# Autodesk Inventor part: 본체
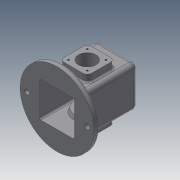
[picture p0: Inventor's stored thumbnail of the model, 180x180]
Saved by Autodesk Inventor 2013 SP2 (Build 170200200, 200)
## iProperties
Created: 2021-08
Part Number: 본체
Material: Generic
Document SubType Name: Modeling
Designer: kumcom8
Density: 1 g/cm^3
Author: kumcom8
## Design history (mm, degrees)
sketch "스케치1"
  geometry: C1 r 67 at (0, 0); 1 further point
  constraints: 1 centre point, 1 coincident
  dimensions: "d0" = 134 diameter of C1
extrude "돌출1" new body sketch "스케치1" distance "d1" = 10; taper "d2" = 0 deg
sketch "스케치2"
  geometry: L1 (-37, -37)-(37, -37); L2 (37, -37)-(37, 37); L3 (37, 37)-(-37, 37); L4 (-37, 37)-(-37, -37); L5 (-37, -37)-(37, 37); L6 (37, -37)-(-37, 37); C1 r 67 at (0, 0) reference
  constraints: 12 end point, 2 midpoint, 2 parallel, 1 horizontal, 1 perpendicular
  dimensions: "d3" = 74 distance of L2.end L3.end; "d5" = 74 distance of L1.end L2.end
extrude "돌출2" join sketch "스케치2" distance "d6" = 100; taper "d7" = 0 deg
sketch "스케치3"
  geometry: L1 (-25, 30)-(25, 30); L2 (25, 30)-(25, 80); L3 (25, 80)-(-25, 80); L4 (-25, 80)-(-25, 30); L5 (-25, 30)-(25, 80); L6 (25, 30)-(-25, 80); L7 (-67, 0)-(67, 0) reference; 3 further points
  constraints: 12 end point, 3 midpoint, 2 parallel, 1 horizontal, 1 perpendicular, 1 vertical alignment
  dimensions: "d8" = 50 distance of L3.end L2.end; "d9" = 50 distance of L2.end L1.end; "d10" = 55 distance from line of L7 point (0, 55)
extrude "돌출3" join sketch "스케치3" stored distance "d11" = 100; taper "d12" = 0 deg
sketch "스케치4"
  geometry: L1 (25, 80)-(-25, 80) reference; L2 (-67, 0)-(67, 0) reference; C1 r 16 at (0, 55); 2 further points
  constraints: 1 centre point, 1 midpoint, 1 vertical alignment
  dimensions: "d13" = 32 diameter of C1; "d14" = 55 distance from line of L2 C1.centre
extrude "돌출4" cut sketch "스케치4" distance "d15" = 110.75; taper "d16" = 0 deg
sketch "스케치5"
  geometry: C1 r 20 at (0, 0); 1 further point
  constraints: 1 centre point, 1 coincident
  dimensions: "d17" = 40 diameter of C1
extrude "돌출5" join sketch "스케치5" distance "d18" = 10; taper "d19" = 0 deg
sketch "스케치6"
  geometry: C1 r 20 at (0, 0) reference; C2 r 10.5 at (0, 0)
  constraints: 1 centre point, 1 coincident
  dimensions: "d20" = 21 diameter of C2
extrude "돌출6" cut sketch "스케치6" distance "d21" = 43.25; taper "d22" = 0 deg
sketch "스케치7"
  geometry: C1 r 10.5 at (0, 0) reference; C2 r 20 at (0, 0) reference; C3 r 14 at (0, 0)
  constraints: 1 centre point, 1 coincident
  dimensions: "d23" = 28 diameter of C3
extrude "돌출7" cut sketch "스케치7" distance "d24" = 4; taper "d25" = 0 deg
feature "면 기울기1" dims angle "d26" = 6 deg
sketch "스케치8"
  geometry: L1 (32, 32)-(-32, 32); L2 (-32, 32)-(-32, -32); L3 (-32, -32)-(32, -32); L4 (32, -32)-(32, 32); L5 (32, 32)-(-32, -32); L6 (-32, 32)-(32, -32); C1 r 67 at (0, 0) reference
  constraints: 12 end point, 2 midpoint, 2 parallel, 1 horizontal, 1 perpendicular
  dimensions: "d27" = 64 distance of L3.end L2.end; "d28" = 64 distance of L2.end L1.end
extrude "돌출8" cut sketch "스케치8" distance "d29" = 105; taper "d30" = 0 deg
sketch "스케치9"
  geometry: C1 r 16 at (32, 55) reference; C2 r 25 at (32, 55); 1 further point
  constraints: 1 centre point, 1 coincident
  dimensions: "d31" = 50 diameter of C2
extrude "돌출9" join sketch "스케치9" distance "d32" = 7; taper "d33" = 0 deg
feature "면 기울기2" dims angle "d34" = 20 deg
feature "면 기울기3" dims angle "d35" = 20 deg
sketch "스케치10"
  geometry: L1 (-17, 38)-(17, 38); L2 (17, 38)-(17, 72); L3 (17, 72)-(-17, 72); L4 (-17, 72)-(-17, 38); L5 (-17, 38)-(17, 72); L6 (17, 38)-(-17, 72); C1 r 16 at (0, 55) reference; 5 further points
  constraints: 12 end point, 4 coincident, 2 midpoint, 2 parallel, 1 horizontal, 1 perpendicular
  dimensions: "d36" = 34 distance of L3.end L2.end; "d37" = 34 distance of L2.end L1.end
hole "구멍1" sketch "스케치10" at (-17, 72), (-17, 38), (17, 38), (17, 72) diameter "d38" = 3.242; stored, may be unused: countersink angle "d42" = 90 deg, drill point angle "d44" = 118 deg; dims "d39" = 8, "d40" = 4, "d41" = 2, "d43" = 10
fillet "모깎기1" dims "d45" = 8
fillet "모깎기2" dims "d46" = 3
sketch "스케치11"
  geometry: C1 r 64 at (0, 0) reference; C2 r 4.5 at (-55, 0); C3 r 4.5 at (55, 0); A1 r 55 centre (0, 0) between (-55, 0) and (55, 0)
  constraints: 3 centre point, 2 point on circle, 1 coincident
  dimensions: "d47" = 110 diameter of A1; "d48" = 9 diameter of C2; "d49" = 9 diameter of C3
extrude "돌출10" cut sketch "스케치11" stored distance "d50" = 7; taper "d51" = 0 deg
node "작업 평면1"
sketch "스케치12"
  geometry: L1 (-37, 102)-(-37, 13) reference; L2 (29, 110)-(-29, 110) reference; L3 (18.949, 120)-(-18.949, 120) reference; 2 further points
  constraints: 1 other
  dimensions: "d53" = 37 distance from line of L1 point (0, 92); "d55" = 28 distance from line of point (0, 92) L3
feature "엠보싱1" sketch "스케치12" dims "d56" = 0.5, "d57" = 0
node "솔리드1"
mirror "대칭1"
mirror "대칭2"
other parameters: "d52" = 0
